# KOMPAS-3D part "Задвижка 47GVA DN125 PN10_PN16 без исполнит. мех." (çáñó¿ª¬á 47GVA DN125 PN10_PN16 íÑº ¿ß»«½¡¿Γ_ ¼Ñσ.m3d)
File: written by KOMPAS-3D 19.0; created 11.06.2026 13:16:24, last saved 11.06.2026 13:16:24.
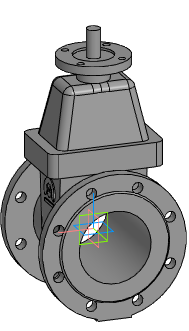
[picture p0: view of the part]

Document properties: Автор: Евгений; Полное имя файла: Z:\3.Личные\kachalov\001_3d для проектировщиков\2.2 Тип 47GVA, 47GVA.Z\_stp\_stp_Задвижка 47GVA DN40-DN1000 без исп.мех\Задвижка 47GVA DN125 PN10_PN16 без исполнит_ мех.m3d

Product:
- Part/product: Задвижка 47GVA DN125 PN10_PN16 без исполнит. мех.

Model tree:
1. Операция без истории:1  (labels: Задвижка 47GVA DN125 PN10_PN16 без исполнит. мех.)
